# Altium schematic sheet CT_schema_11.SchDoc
size 742 x 377 mm
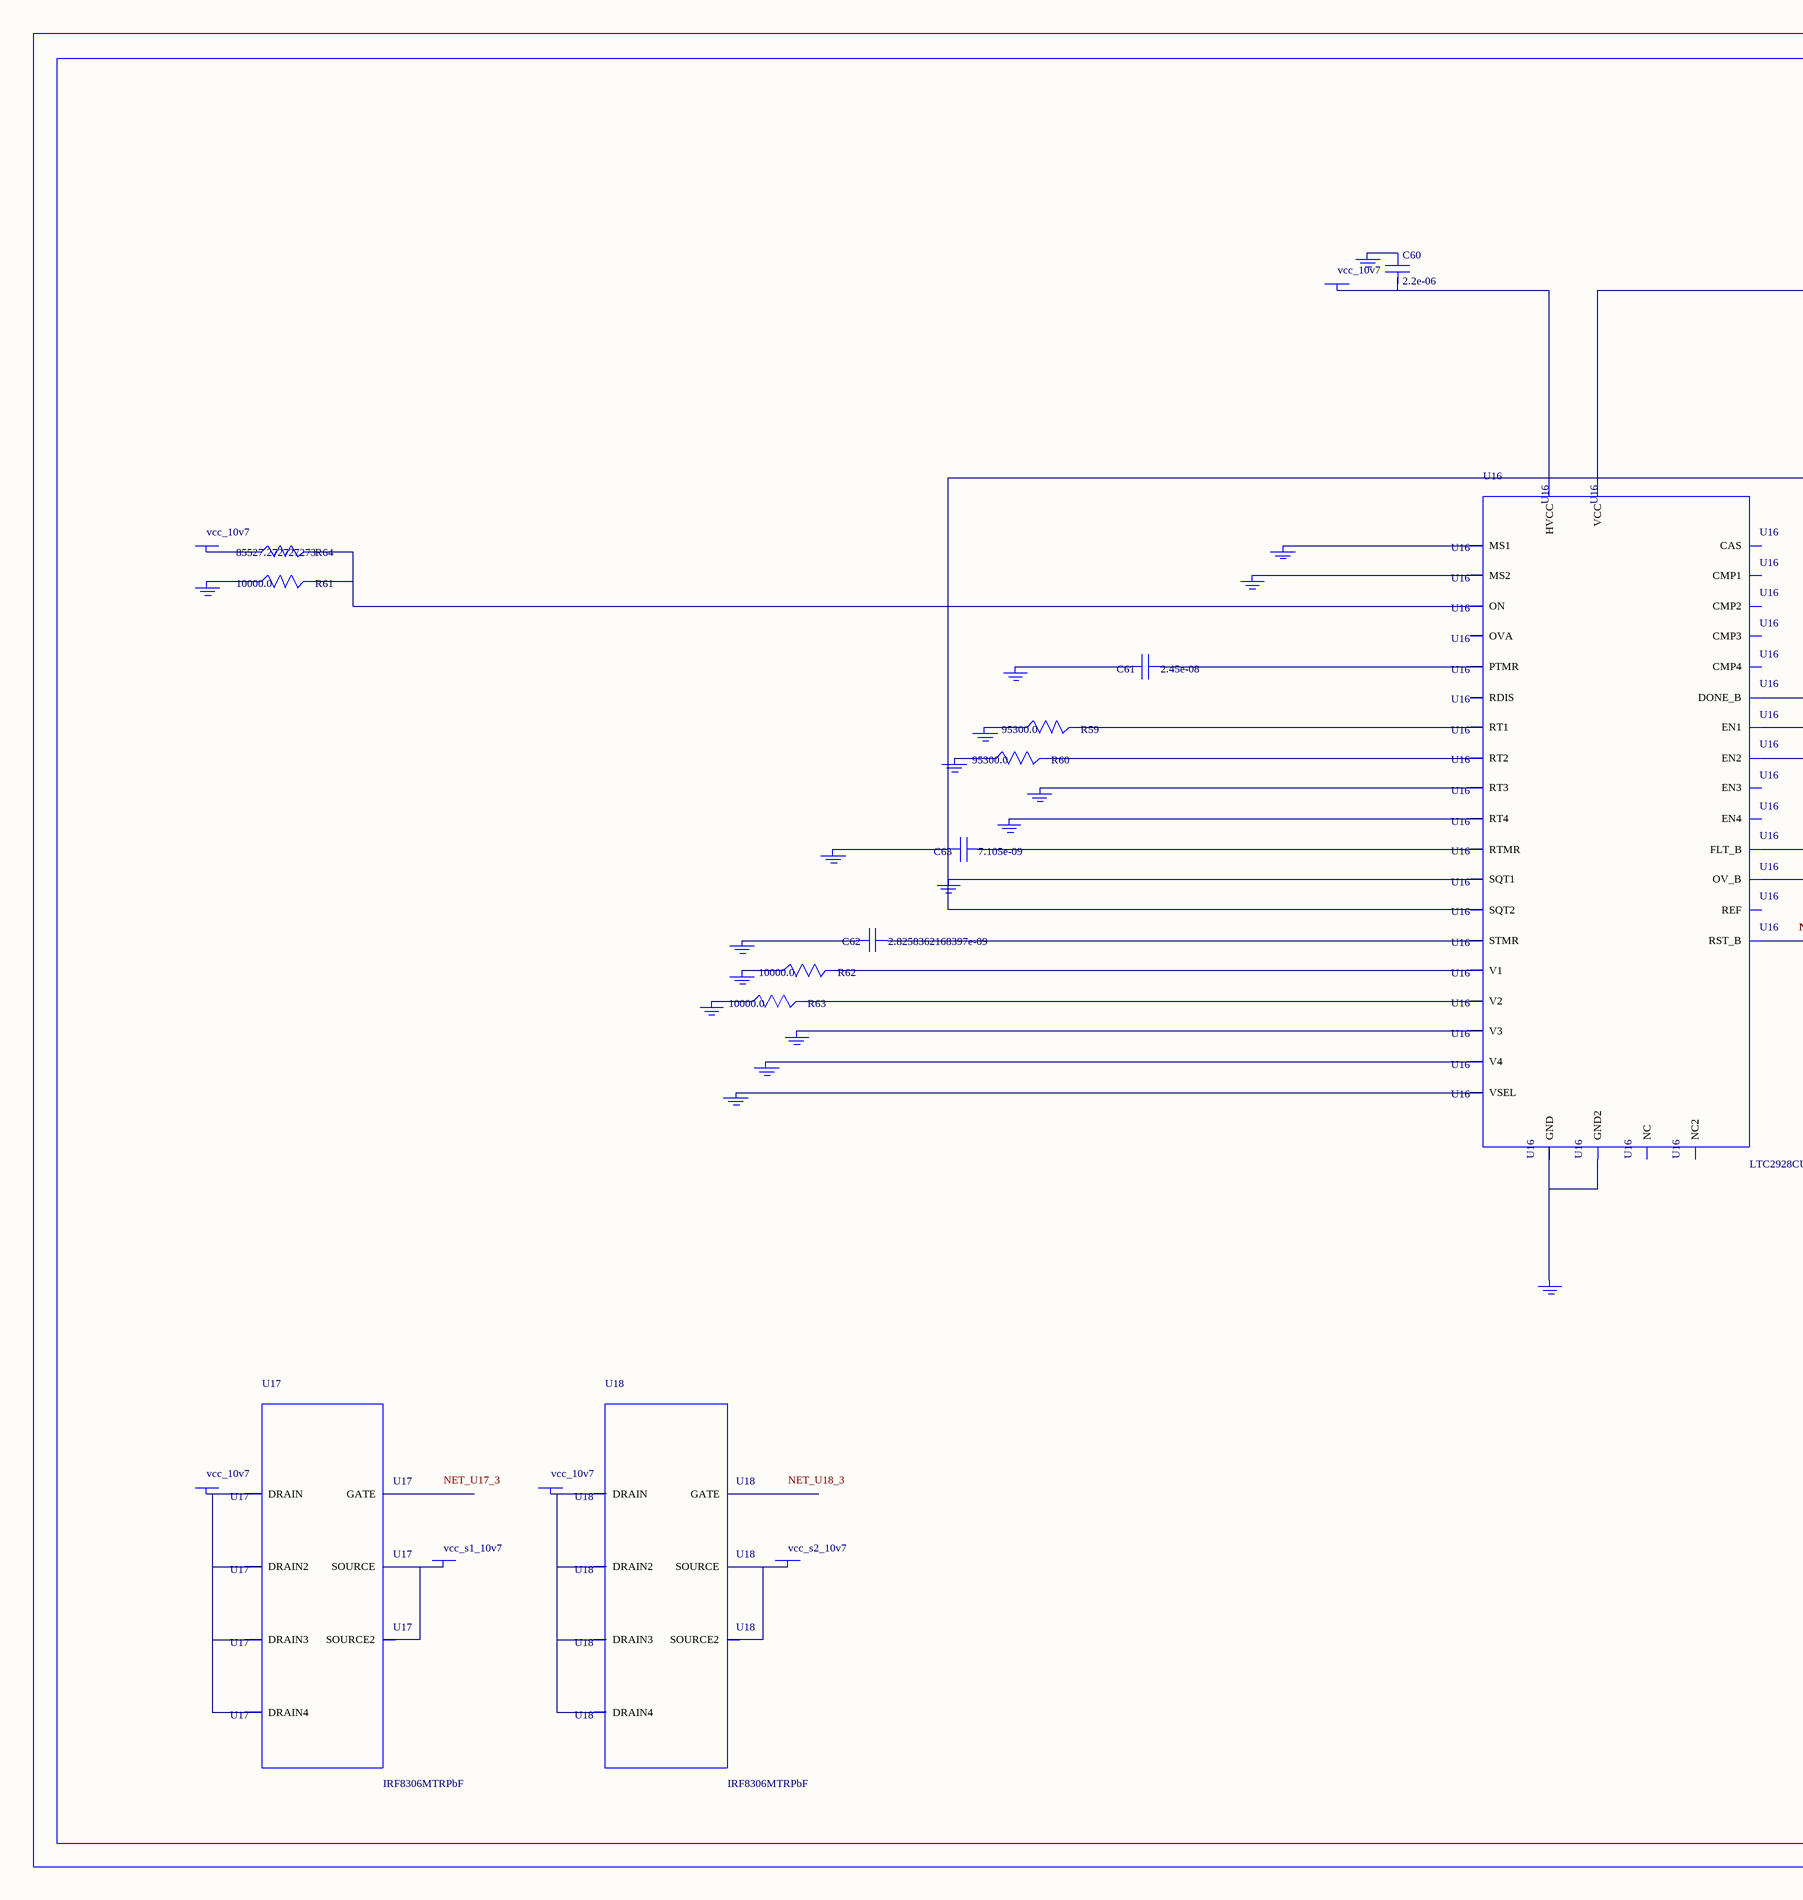
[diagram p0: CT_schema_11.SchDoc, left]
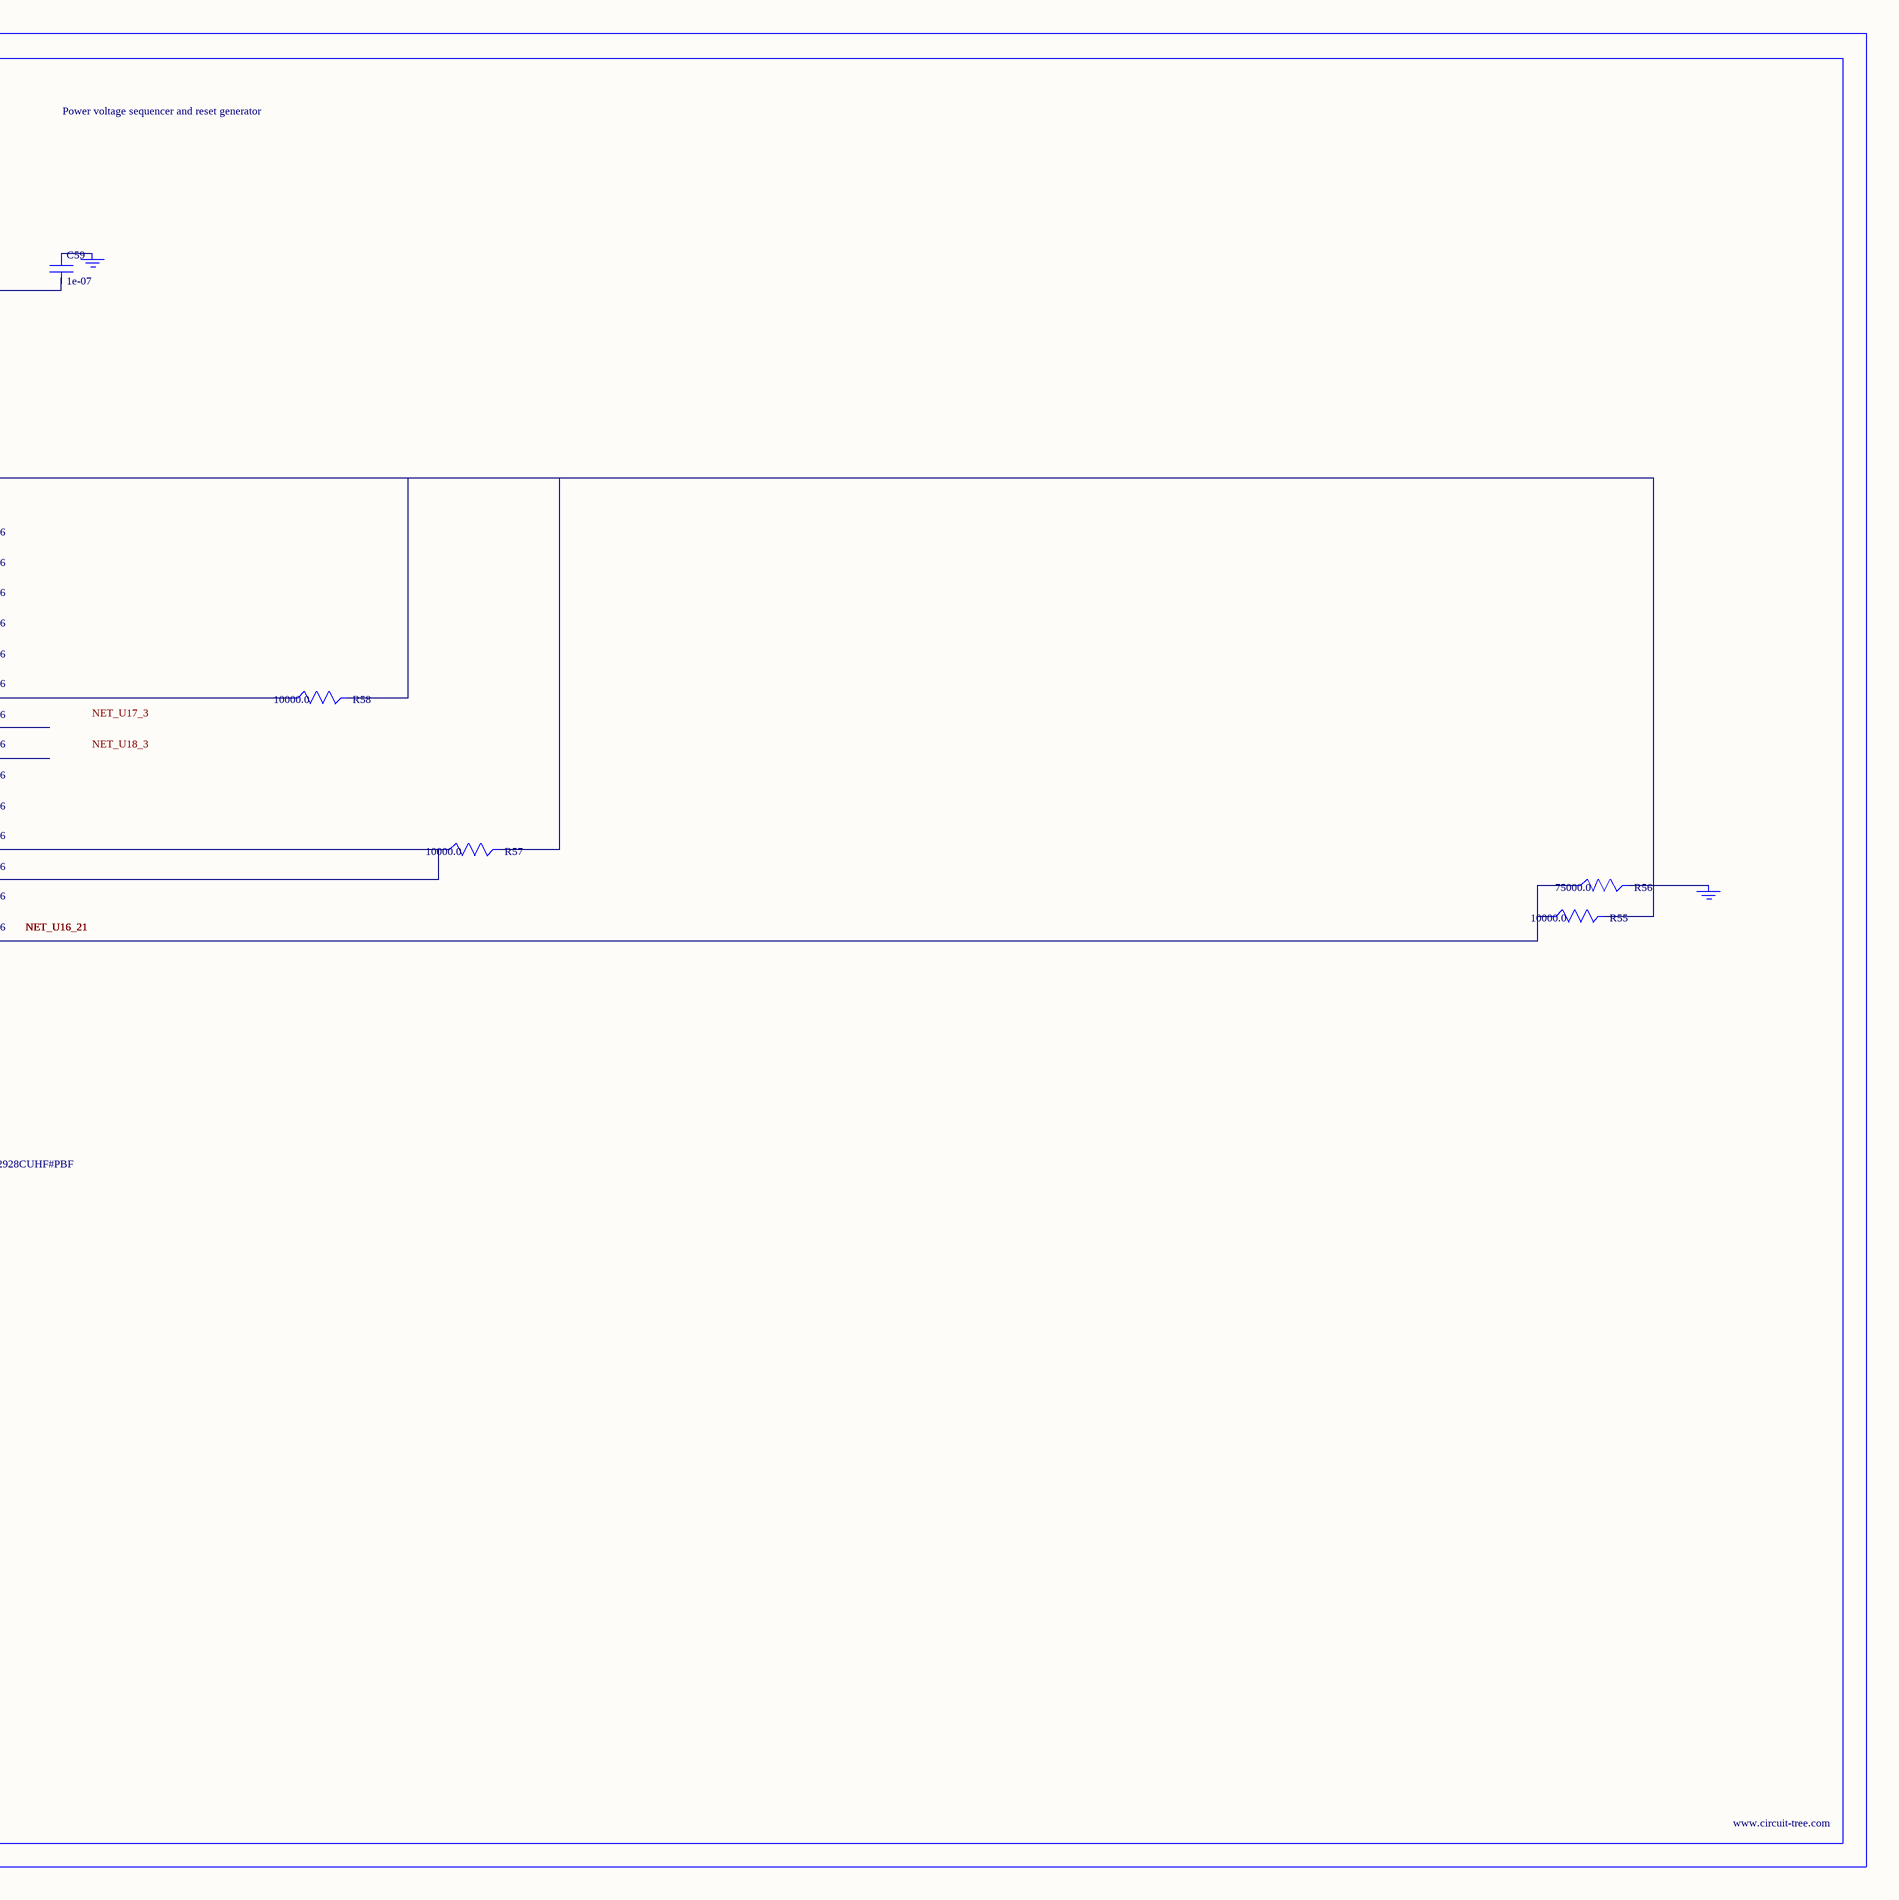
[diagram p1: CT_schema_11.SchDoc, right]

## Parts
BORDER10  (no value)
C59  1e-07  [C0402]
C60  2.2e-06  [C0603]
C61  2.45e-08  [R0603]
C62  2.8258362168397e-09  [R0603]
C63  7.105e-09  [R0603]
GND_INSTANCE_10_0  (no value)
GND_INSTANCE_10_1  (no value)
GND_INSTANCE_10_2  (no value)
GND_INSTANCE_10_3  (no value)
GND_INSTANCE_10_4  (no value)
GND_INSTANCE_10_5  (no value)
GND_INSTANCE_10_6  (no value)
GND_INSTANCE_10_7  (no value)
GND_INSTANCE_10_8  (no value)
GND_INSTANCE_10_9  (no value)
GND_INSTANCE_10_10  (no value)
GND_INSTANCE_10_11  (no value)
GND_INSTANCE_10_12  (no value)
GND_INSTANCE_10_13  (no value)
GND_INSTANCE_10_14  (no value)
GND_INSTANCE_10_15  (no value)
GND_INSTANCE_10_16  (no value)
GND_INSTANCE_10_17  (no value)
GND_INSTANCE_10_18  (no value)
GND_INSTANCE_10_19  (no value)
POWER_INSTANCE_10_0  vcc_10v7
POWER_INSTANCE_10_1  vcc_10v7
POWER_INSTANCE_10_2  vcc_10v7
POWER_INSTANCE_10_3  vcc_s1_10v7
POWER_INSTANCE_10_4  vcc_10v7
POWER_INSTANCE_10_5  vcc_s2_10v7
R55  10000.0  [R0603]
R56  75000.0  [R0603]
R57  10000.0  [R0603]
R58  10000.0  [R0603]
R59  95300.0  [R0603]
R60  95300.0  [R0603]
R61  10000.0  [R0603]
R62  10000.0  [R0603]
R63  10000.0  [R0603]
R64  85527.272727273  [R0603]
U16  LTC2928CUHF#PBF  [QFN-38_UHF]
U17  IRF8306MTRPbF  [IRF8306MTRPBF]
U18  IRF8306MTRPbF  [IRF8306MTRPBF]

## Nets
NetC59_1: C59.1 GND_INSTANCE_10_10.0(GND)
NetC59_2: C59.2 C63.2 GND_INSTANCE_10_5.0(GND) GND_INSTANCE_10_15.0(GND) R55.2 R57.2 R58.2 U16.10(SQT1) U16.11(SQT2) U16.22(VCC)
NetC60_1: C60.1 GND_INSTANCE_10_11.0(GND)
NetC60_2: C60.2 POWER_INSTANCE_10_1.0(PWR) U16.23(HVCC)
NetC61_1: C61.1 U16.27(PTMR)
NetC61_2: C61.2 GND_INSTANCE_10_14.0(GND)
NetC62_1: C62.1 U16.26(STMR)
NetC62_2: C62.2 GND_INSTANCE_10_13.0(GND)
NetC63_1: C63.1 U16.28(RTMR)
NetGND_INSTANCE_10_0_0: GND_INSTANCE_10_0.0(GND) R62.1
NetGND_INSTANCE_10_1_0: GND_INSTANCE_10_1.0(GND) R59.1
NetGND_INSTANCE_10_2_0: GND_INSTANCE_10_2.0(GND) R60.1
NetGND_INSTANCE_10_3_0: GND_INSTANCE_10_3.0(GND) U16.8(RT3)
NetGND_INSTANCE_10_4_0: GND_INSTANCE_10_4.0(GND) U16.9(RT4)
NetGND_INSTANCE_10_6_0: GND_INSTANCE_10_6.0(GND) U16.12(MS1)
NetGND_INSTANCE_10_7_0: GND_INSTANCE_10_7.0(GND) U16.13(MS2)
NetGND_INSTANCE_10_8_0: GND_INSTANCE_10_8.0(GND) R61.1
NetGND_INSTANCE_10_9_0: GND_INSTANCE_10_9.0(GND) R56.2
NetGND_INSTANCE_10_12_0: GND_INSTANCE_10_12.0(GND) U16.25(VSEL)
NetGND_INSTANCE_10_16_0: GND_INSTANCE_10_16.0(GND) U16.30(V4)
NetGND_INSTANCE_10_17_0: GND_INSTANCE_10_17.0(GND) U16.32(V3)
NetGND_INSTANCE_10_18_0: GND_INSTANCE_10_18.0(GND) R63.1
NetGND_INSTANCE_10_19_0: GND_INSTANCE_10_19.0(GND) U16.24(GND) U16.39(GND2)
NetPOWER_INSTANCE_10_0_0: POWER_INSTANCE_10_0.0(PWR) R64.1
NetPOWER_INSTANCE_10_2_0: POWER_INSTANCE_10_2.0(PWR) U17.1(DRAIN) U17.2(DRAIN2) U17.6(DRAIN3) U17.7(DRAIN4)
NetPOWER_INSTANCE_10_3_0: POWER_INSTANCE_10_3.0(PWR) U17.4(SOURCE) U17.5(SOURCE2)
NetPOWER_INSTANCE_10_4_0: POWER_INSTANCE_10_4.0(PWR) U18.1(DRAIN) U18.2(DRAIN2) U18.6(DRAIN3) U18.7(DRAIN4)
NetPOWER_INSTANCE_10_5_0: POWER_INSTANCE_10_5.0(PWR) U18.4(SOURCE) U18.5(SOURCE2)
NetR55_1: R55.1 R56.1 U16.21(RST_B)
NetR57_1: R57.1 U16.19(FLT_B) U16.20(OV_B)
NetR58_1: R58.1 U16.18(DONE_B)
NetR59_2: R59.2 U16.6(RT1)
NetR60_2: R60.2 U16.7(RT2)
NetR61_2: R61.2 R64.2 U16.16(ON)
NetR62_2: R62.2 U16.3(V1)
NetR63_2: R63.2 U16.38(V2)

Not connected (* = marked no-connect by the designer): U16 1(OVA) 2(EN1) 4(NC) 5(REF) 14(RDIS) 15(CAS) 17(NC2) 29(EN4) 31(EN3) 33(CMP3) 34(CMP4) 35(CMP1) 36(CMP2) 37(EN2); U17 3(GATE); U18 3(GATE)

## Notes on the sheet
- Labels drawn without touching a wire or pin: NET_U17_3, NET_U18_3

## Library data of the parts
BORDER10 = BORDER_PAGE10
C59 = C0402C104K3RACTU
C60 = GRM188R61H225KE1115D
C61 = C61
C62 = C62
C63 = C63
GND_INSTANCE_10_0-GND_INSTANCE_10_19 = GND
POWER_INSTANCE_10_0-POWER_INSTANCE_10_5 = PWR
R55 R57 R58 R61-R63 = RC0603JR-0710KL
R56 = RC0603JR-0775KL
R59 R60 = RC0603FR-0795K3L
R64 = R64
